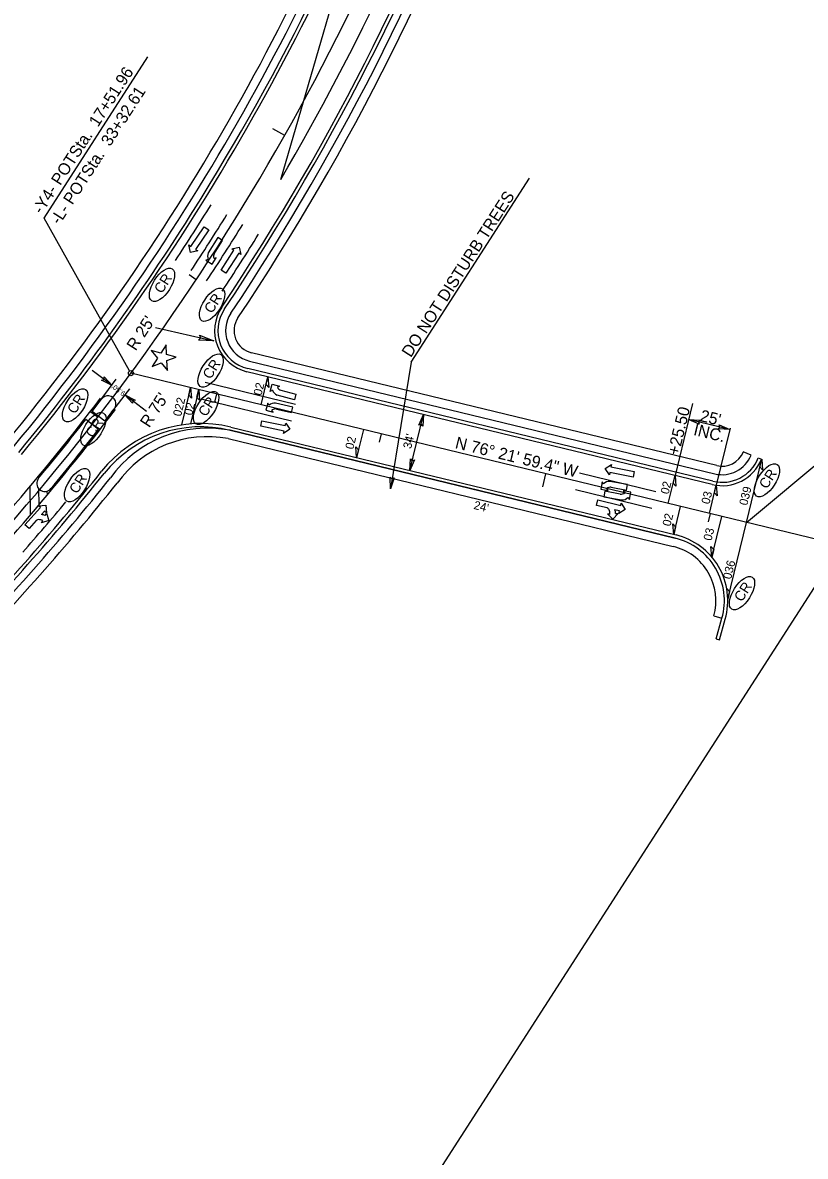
# Model space of a CAD drawing. Extents: x 1974386 to 1979988, y 776712 to 784860.
# Drawn here: x 1977051 to 1977514, y 779824 to 780494 of the extents above; entities that cross this region are included whole.
import ezdxf

# ---------------------------------------------------------------- set-up
doc = ezdxf.new("R2010")
doc.units = 0
for name, color, linetype in [('Prop Conc 2ft 6in Curb and Gutter', 7, 'Continuous'), ('Prop Conc 4in Sidewalk', 7, 'Continuous'), ('Prop Conc 5in Monolithic Keyed In Island', 7, 'Continuous'), ('Prop Conc Drive Drop Type', 7, 'Continuous'), ('Prop Dimension', 7, 'Continuous'), ('Prop Dimension Text', 7, 'Continuous'), ('Prop DSN Text', 7, 'Continuous'), ('Prop EOT', 7, 'Continuous'), ('Prop Horizontal Alignment', 7, 'Continuous'), ('Prop Horizontal Alignment Direction Label', 7, 'Continuous'), ('Prop Horizontal Alignment Station Label', 7, 'Continuous'), ('Prop Horizontal Alignment Tick Large', 7, 'Continuous'), ('Prop Horizontal Alignment Tick Small', 7, 'Continuous'), ('Prop Lane Arrow CELL', 7, 'Continuous'), ('Prop Lane Lines', 7, 'Continuous'), ('Prop RDY Traffic Signal CELL', 7, 'Continuous'), ('Prop Superelevation  Arrow CELL', 7, 'Continuous'), ('Prop Superelevation Label', 7, 'Continuous'), ('Prop Terminator CELL', 7, 'Continuous'), ('Prop WCC CELL', 7, 'Continuous'), ('Scratch_Level_2', 7, 'Continuous'), ('Sheet Layout Plan Border', 7, 'Continuous')]:
    doc.layers.add(name, color=color, linetype=linetype)

msp = doc.modelspace()

# ---------------------------------------------------------------- linework, layer by layer
at = {"layer": 'Prop Conc 2ft 6in Curb and Gutter'}
for p, q in [((1977459.07, 780223.06), (1977184.38, 780289.69)), ((1977173.94, 780253.12), (1977436.77, 780189.37)), ((1977485.82, 780236.94), (1977487.67, 780236.05)), ((1977460.97, 780129.99), (1977464.4, 780142.14)), ((1977460.97, 780129.99), (1977462.9, 780129.45))]:
    msp.add_line(p, q, dxfattribs=at)
for centre, radius, start, end in [((1975987.1, 781115.69), 1376.5, 328.18457, 340.62647), ((1975987.1, 781115.69), 1423.5, 326.24911, 340.62647), ((1975987.1, 781115.69), 1376.5, 320.49711, 328.18457), ((1977189.8, 780312.04), 23, 146.24911, 256.36649), ((1977156.74, 780182.17), 73, 76.36649, 141.40587), ((1977464.49, 780245.41), 23, 256.36649, 338.00929), ((1975987.1, 781115.69), 1423.5, 315.73946, 321.40587), ((1977427.82, 780152.44), 38, 344.27883, 76.36649)]:
    msp.add_arc(centre, radius, start, end, dxfattribs=at)
at = {"layer": 'Prop Conc 4in Sidewalk'}
for p, q in [((1977185.44, 780294.06), (1977460.13, 780227.44)), ((1977461.3, 780232.29), (1977186.62, 780298.92)), ((1977436.77, 780189.37), (1977173.94, 780253.12)), ((1977172.77, 780248.26), (1977435.6, 780184.51)), ((1977172.77, 780248.26), (1977435.6, 780184.51)), ((1977481.64, 780238.49), (1977477, 780240.36)), ((1977459.58, 780143.5), (1977464.4, 780142.14)), ((1977459.58, 780143.5), (1977464.4, 780142.14))]:
    msp.add_line(p, q, dxfattribs=at)
for centre, radius, start, end in [((1975987.1, 781115.69), 1367, 320.45193, 340.62647), ((1975987.1, 781115.69), 1372, 320.5086, 340.62647), ((1975987.1, 781115.69), 1428, 326.24911, 340.62647), ((1975987.1, 781115.69), 1433, 326.24911, 340.62647), ((1977189.8, 780312.04), 18.5, 146.24911, 256.36649), ((1977189.8, 780312.04), 13.5, 146.24911, 256.36649), ((1977160.63, 780183.72), 70.66, 79.13925, 144.17863), ((1977160.63, 780183.72), 70.66, 79.13925, 144.17863), ((1977160.63, 780183.72), 65.66, 79.34999, 144.38937), ((1977160.63, 780183.72), 65.66, 79.34999, 144.38937), ((1977464.49, 780245.41), 13.5, 256.36649, 338.00929), ((1977464.49, 780245.41), 18.5, 256.36649, 338.00929), ((1975987.1, 781115.69), 1428, 315.73946, 321.41478), ((1975987.1, 781115.69), 1428, 315.73946, 321.41478), ((1975987.1, 781115.69), 1433, 315.73946, 321.41478), ((1975987.1, 781115.69), 1433, 315.73946, 321.41478), ((1977427.82, 780152.44), 38, 344.27883, 76.36649), ((1977427.82, 780152.44), 33, 344.27883, 76.36649), ((1977427.82, 780152.44), 33, 344.27883, 76.36649)]:
    msp.add_arc(centre, radius, start, end, dxfattribs=at)
at = {"layer": 'Prop Conc 5in Monolithic Keyed In Island'}
for p, q in [((1977096.29, 780253.7), (1977088.79, 780259.54)), ((1977099.96, 780258.45), (1977092.46, 780264.29))]:
    msp.add_line(p, q, dxfattribs=at)
for centre, radius, start, end in [((1977101.86, 780268.75), 4.75, 322.77439, 142.77439), ((1975987.1, 781115.69), 1395.25, 322.39493, 322.77439), ((1975987.1, 781115.69), 1404.75, 322.39283, 322.77439), ((1975987.1, 781115.69), 1395.25, 320.31886, 322.14854), ((1975987.1, 781115.69), 1404.75, 320.31886, 322.14811), ((1977064.55, 780221.77), 4.75, 140.31886, 320.31886)]:
    msp.add_arc(centre, radius, start, end, dxfattribs=at)
at = {"layer": 'Prop Conc Drive Drop Type'}
msp.add_line((1977337.66, 780213.41), (1977314.34, 780219.06), dxfattribs=at)
at = {"layer": 'Prop Dimension'}
for p, q in [((1977129.82, 780313.77), (1977164.4, 780305.93)), ((1977104.26, 780279.65), (1977092.58, 780288.52)), ((1977092.45, 780264.29), (1977106.72, 780283.38)), ((1977099.96, 780258.45), (1977114.76, 780277.64)), ((1977124.61, 780264.31), (1977111.74, 780274.09)), ((1977446.99, 780269.01), (1977436.66, 780226.44)), ((1977280.11, 780229.42), (1977288.12, 780262.47)), ((1977468.98, 780253.63), (1977444.68, 780259.52)), ((1977469.16, 780254.38), (1977460.98, 780220.66))]:
    msp.add_line(p, q, dxfattribs=at)
at = {"layer": 'Prop DSN Text'}
for q in [(1977350.71, 780402.12), (1977268.62, 780218.57)]:
    msp.add_line((1977280.93, 780293.47), q, dxfattribs=at)
at = {"layer": 'Prop EOT'}
for p, q in [((1977458.59, 780221.12), (1977183.91, 780287.74)), ((1977174.42, 780255.06), (1977437.25, 780191.31)), ((1977462.9, 780129.45), (1977466.32, 780141.6))]:
    msp.add_line(p, q, dxfattribs=at)
for centre, radius, start, end in [((1975987.1, 781115.69), 1378.5, 320.50095, 340.62647), ((1975987.1, 781115.69), 1421.5, 326.24911, 340.61773), ((1977189.8, 780312.04), 25, 146.24911, 256.36649), ((1977156.74, 780182.17), 75, 76.36649, 141.40587), ((1977464.49, 780245.41), 25, 256.36649, 338.00929), ((1975987.1, 781115.69), 1421.5, 315.73946, 321.40587), ((1977427.82, 780152.44), 40, 344.27883, 76.36649)]:
    msp.add_arc(centre, radius, start, end, dxfattribs=at)
at = {"layer": 'Prop Horizontal Alignment'}
msp.add_line((1977701.03, 780144.83), (1977115.39, 780286.87), dxfattribs=at)
msp.add_arc((1975987.1, 781115.69), 1400, 315.73946, 340.62647, dxfattribs=at)
at = {"layer": 'Prop Horizontal Alignment Station Label'}
for p, q in [((1977064.11, 780378.45), (1977125.46, 780473.84)), ((1977114.66, 780288.18), (1977064.11, 780378.45)), ((1977478.82, 780198.72), (1977566.67, 780272.16))]:
    msp.add_line(p, q, dxfattribs=at)
msp.add_circle((1977115.39, 780286.87), 1.5, dxfattribs=at)
at = {"layer": 'Prop Horizontal Alignment Tick Large'}
for p, q in [((1977206.2, 780427.36), (1977199.23, 780431.3)), ((1977360.25, 780227.48), (1977358.37, 780219.7))]:
    msp.add_line(p, q, dxfattribs=at)
at = {"layer": 'Prop Horizontal Alignment Tick Small'}
for p, q in [((1977153.97, 780342.11), (1977149.8, 780344.88)), ((1977165.89, 780274.62), (1977164.71, 780269.76)), ((1977095.78, 780260.81), (1977091.82, 780263.86)), ((1977263.07, 780251.05), (1977261.89, 780246.19)), ((1977457.43, 780203.91), (1977456.26, 780199.05)), ((1977457.43, 780203.91), (1977456.26, 780199.05)), ((1977457.43, 780203.91), (1977456.26, 780199.05))]:
    msp.add_line(p, q, dxfattribs=at)
at = {"layer": 'Prop Lane Arrow CELL'}
for p, q in [((1977150.84, 780361.78), (1977158.65, 780373.4)), ((1977158.65, 780373.4), (1977161.39, 780371.56)), ((1977161.39, 780371.56), (1977153.58, 780359.94)), ((1977166.66, 780366.96), (1977161.09, 780358.01)), ((1977169.46, 780365.22), (1977166.66, 780366.96)), ((1977150.49, 780358.22), (1977149.59, 780362.62)), ((1977149.59, 780362.62), (1977150.84, 780361.78)), ((1977153.58, 780359.94), (1977154.82, 780359.1)), ((1977164.63, 780357.45), (1977169.46, 780365.22)), ((1977168.65, 780347.79), (1977176.26, 780359.55)), ((1977175, 780360.36), (1977179.31, 780361.32)), ((1977176.26, 780359.55), (1977175, 780360.36)), ((1977179.31, 780361.32), (1977180.29, 780356.94)), ((1977154.82, 780359.1), (1977150.49, 780358.22)), ((1977161.05, 780353.97), (1977159.6, 780353.63)), ((1977159.6, 780353.63), (1977163.31, 780351.26)), ((1977163.31, 780351.26), (1977165.73, 780355.06)), ((1977165.73, 780355.06), (1977164.28, 780354.72)), ((1977179.03, 780357.75), (1977171.42, 780346)), ((1977180.29, 780356.94), (1977179.03, 780357.75)), ((1977171.42, 780346), (1977168.65, 780347.79)), ((1977197.7, 780276.15), (1977198.8, 780280.41)), ((1977198.8, 780280.41), (1977203.16, 780279.29)), ((1977203.16, 780279.29), (1977201.87, 780278.55)), ((1977198.99, 780276.89), (1977197.7, 780276.15)), ((1977211.95, 780271.21), (1977201.77, 780273.96)), ((1977203.98, 780276.78), (1977212.82, 780274.39)), ((1977212.82, 780274.39), (1977211.95, 780271.21)), ((1977196.15, 780269.21), (1977195.09, 780264.94)), ((1977196.93, 780267.95), (1977196.15, 780269.21)), ((1977211.04, 780266.78), (1977200.77, 780269.2)), ((1977201.38, 780265.67), (1977210.28, 780263.57)), ((1977210.28, 780263.57), (1977211.04, 780266.78)), ((1977195.09, 780264.94), (1977199.46, 780263.86)), ((1977199.46, 780263.86), (1977198.68, 780265.12)), ((1977192.11, 780255.49), (1977192.78, 780258.73)), ((1977205.83, 780252.68), (1977192.11, 780255.49)), ((1977192.78, 780258.73), (1977206.49, 780255.91)), ((1977209.26, 780253.71), (1977205.53, 780251.21)), ((1977205.53, 780251.21), (1977205.83, 780252.68)), ((1977206.49, 780255.91), (1977206.79, 780257.38)), ((1977206.79, 780257.38), (1977209.26, 780253.71)), ((1977395.43, 780230.48), (1977399.16, 780232.98)), ((1977399.16, 780232.98), (1977398.86, 780231.51)), ((1977397.89, 780226.81), (1977395.43, 780230.48)), ((1977398.19, 780228.28), (1977397.89, 780226.81)), ((1977411.91, 780225.46), (1977398.19, 780228.28)), ((1977398.86, 780231.51), (1977412.57, 780228.7)), ((1977412.57, 780228.7), (1977411.91, 780225.46)), ((1977393.6, 780222.72), (1977392.78, 780218.39)), ((1977394.45, 780221.5), (1977393.6, 780222.72)), ((1977397.2, 780217.55), (1977396.35, 780218.77)), ((1977408.6, 780221.09), (1977398.22, 780222.95)), ((1977399.01, 780219.46), (1977408.02, 780217.84)), ((1977408.02, 780217.84), (1977408.6, 780221.09)), ((1977390.39, 780208.8), (1977391.17, 780212.01)), ((1977391.17, 780212.01), (1977404.58, 780208.72)), ((1977392.78, 780218.39), (1977397.2, 780217.55)), ((1977395.31, 780217.09), (1977394.73, 780213.84)), ((1977394.73, 780213.84), (1977405.11, 780211.98)), ((1977404.32, 780215.48), (1977395.31, 780217.09)), ((1977410.55, 780216.54), (1977406.13, 780217.38)), ((1977406.13, 780217.38), (1977406.98, 780216.17)), ((1977408.88, 780213.44), (1977409.72, 780212.22)), ((1977409.72, 780212.22), (1977410.55, 780216.54)), ((1977052.79, 780197.28), (1977061.92, 780207.62)), ((1977060.8, 780208.61), (1977065.21, 780208.85)), ((1977061.92, 780207.62), (1977060.8, 780208.61)), ((1977064.39, 780205.44), (1977062.51, 780203.3)), ((1977065.52, 780204.44), (1977064.39, 780205.44)), ((1977065.21, 780208.85), (1977065.52, 780204.44)), ((1977396.65, 780207.26), (1977390.39, 780208.8)), ((1977403.79, 780205.51), (1977401.02, 780206.19)), ((1977407.19, 780206.37), (1977403.43, 780204.05)), ((1977403.43, 780204.05), (1977403.79, 780205.51)), ((1977404.58, 780208.72), (1977404.93, 780210.17)), ((1977404.93, 780210.17), (1977407.19, 780206.37)), ((1977059.53, 780199.93), (1977055.26, 780195.09)), ((1977066.9, 780199.89), (1977062.7, 780198.46)), ((1977062.7, 780198.46), (1977063.33, 780199.77)), ((1977064.81, 780202.73), (1977065.47, 780204.09)), ((1977065.47, 780204.09), (1977066.9, 780199.89)), ((1977396.82, 780203.77), (1977398.28, 780203.83)), ((1977400.04, 780200.72), (1977396.82, 780203.77)), ((1977403.09, 780203.93), (1977400.04, 780200.72)), ((1977401.59, 780203.89), (1977403.09, 780203.93)), ((1977055.26, 780195.09), (1977052.79, 780197.28))]:
    msp.add_line(p, q, dxfattribs=at)
for centre, radius, start, end in [((1977165.9, 780355.94), 5.25, 156.78047, 202.09216), ((1977167.39, 780355.72), 3.27, 148.1044, 197.76257), ((1977203.89, 780278.75), 5.25, 200.86938, 246.18108), ((1977204.82, 780279.93), 3.27, 205.19898, 254.85715), ((1977200.36, 780263.98), 5.25, 85.40152, 130.71321), ((1977200.62, 780262.5), 3.27, 76.72544, 126.38362), ((1977398.08, 780217.72), 5.25, 88.49449, 133.80619), ((1977398.43, 780216.25), 3.27, 79.81842, 129.47659), ((1977404.9, 780218.68), 3.27, 259.81842, 309.47659), ((1977405.25, 780217.21), 5.25, 268.49449, 313.80619), ((1977395.45, 780205.04), 2.52, 25.27738, 61.58938), ((1977393.84, 780203.99), 4.43, 357.91391, 28.76747), ((1977397.15, 780204.06), 4.43, 357.7951, 28.6737), ((1977060.94, 780197.83), 2.52, 87.62766, 123.93966), ((1977061.13, 780195.92), 4.43, 60.26419, 91.11775), ((1977062.6, 780198.88), 4.43, 60.14538, 91.02398)]:
    msp.add_arc(centre, radius, start, end, dxfattribs=at)
at = {"layer": 'Prop Lane Lines'}
for p, q in [((1977212.6, 780268.44), (1977159.29, 780281.37)), ((1977156.93, 780271.65), (1977210.24, 780258.72)), ((1977425.35, 780216.83), (1977380.2, 780227.78)), ((1977056.2, 780203.3), (1977055.98, 780220.08)), ((1977061.13, 780209.11), (1977061, 780218.61)), ((1977066.05, 780214.97), (1977066.02, 780217.25)), ((1977377.85, 780218.07), (1977422.99, 780207.12))]:
    msp.add_line(p, q, dxfattribs=at)
for radius, start, end in [(1383.5, 326.57123, 328.18415), (1394.5, 326.57123, 328.18415), (1405.5, 326.57123, 328.18415), (1416.5, 326.57123, 328.18415), (1394.5, 315.73946, 322.77439), (1405.5, 315.73946, 322.77439), (1416.5, 318.71501, 320.29496)]:
    msp.add_arc((1975987.1, 781115.69), radius, start, end, dxfattribs=at)
at = {"layer": 'Prop RDY Traffic Signal CELL'}
msp.add_lwpolyline([(1977131.03, 780295.74), (1977127.89, 780290.86), (1977133.3, 780292.96), (1977136.98, 780288.46), (1977136.65, 780294.27), (1977142.07, 780296.38), (1977136.45, 780297.85), (1977136.12, 780303.65), (1977132.98, 780298.77), (1977127.35, 780300.24), (1977131.03, 780295.74)], dxfattribs=at)
at = {"layer": 'Prop Superelevation  Arrow CELL'}
for p, q in [((1977192.32, 780268.21), (1977196.32, 780284.73)), ((1977150.6, 780278.33), (1977145.26, 780256.29)), ((1977155.46, 780277.15), (1977150.55, 780256.92)), ((1977252.64, 780253.58), (1977248.64, 780237.06)), ((1977478.82, 780198.72), (1977487.86, 780236.02)), ((1977432.65, 780209.92), (1977436.66, 780226.44)), ((1977456.95, 780204.02), (1977460.98, 780220.66)), ((1977435.94, 780191.63), (1977439.94, 780208.15)), ((1977458.41, 780178.21), (1977464.24, 780202.26)), ((1977467.81, 780153.33), (1977478.82, 780198.72))]:
    msp.add_line(p, q, dxfattribs=at)
for points in [[(1977196.32, 780284.73), (1977196.85, 780278.43), (1977195.23, 780280.24)], [(1977150.6, 780278.33), (1977151.13, 780272.03), (1977149.51, 780273.83)], [(1977155.46, 780277.15), (1977155.99, 780270.85), (1977154.37, 780272.65)], [(1977248.64, 780237.06), (1977248.11, 780243.36), (1977249.73, 780241.55)], [(1977487.86, 780236.02), (1977488.39, 780229.72), (1977486.77, 780231.53)], [(1977436.66, 780226.44), (1977437.19, 780220.14), (1977435.57, 780221.94)], [(1977460.98, 780220.66), (1977461.51, 780214.36), (1977459.89, 780216.17)], [(1977435.94, 780191.63), (1977435.41, 780197.93), (1977437.03, 780196.12)], [(1977458.41, 780178.21), (1977457.88, 780184.51), (1977459.5, 780182.71)], [(1977467.81, 780153.33), (1977467.28, 780159.64), (1977468.9, 780157.83)]]:
    msp.add_lwpolyline(points, close=True, dxfattribs=at)
at = {"layer": 'Prop Terminator CELL'}
for points in [[(1977155.97, 780309.43), (1977164.4, 780305.93), (1977155.22, 780306.37), (1977156.7, 780307.68)], [(1977099.58, 780284.66), (1977104.26, 780279.65), (1977098.12, 780282.8), (1977099.54, 780283.24)], [(1977116.41, 780269.08), (1977111.74, 780274.09), (1977117.87, 780270.94), (1977116.46, 780270.51)], [(1977285.4, 780256.18), (1977288.12, 780262.47), (1977287.69, 780255.59), (1977286.73, 780256.71)], [(1977450.97, 780256.8), (1977444.68, 780259.52), (1977451.56, 780259.09), (1977450.44, 780258.13)], [(1977462.69, 780256.35), (1977468.98, 780253.63), (1977462.1, 780254.06), (1977463.22, 780255.03)], [(1977282.83, 780235.71), (1977280.11, 780229.42), (1977280.54, 780236.3), (1977281.5, 780235.18)], [(1977270.86, 780225.05), (1977268.62, 780218.57), (1977268.53, 780225.47), (1977269.58, 780224.42)]]:
    msp.add_lwpolyline(points, close=True, dxfattribs=at)
at = {"layer": 'Prop WCC CELL'}
for centre in [(1977133.76, 780339.05), (1977163.33, 780327.29), (1977162.43, 780288.42), (1977082.45, 780267.88), (1977159.79, 780266.3), (1977093.22, 780253.79), (1977490.92, 780223.59), (1977083.63, 780220.74), (1977476.21, 780156.91)]:
    msp.add_ellipse(centre, major_axis=(6.07, 9.43), ratio=0.462467, dxfattribs=at)
at = {"layer": 'Scratch_Level_2'}
msp.add_line((1977203.85, 780401.24), (1977333.59, 780846.18), dxfattribs=at)
msp.add_arc((1975987.1, 781115.69), 1411, 329.5795, 340.62647, dxfattribs=at)
at = {"layer": 'Sheet Layout Plan Border'}
msp.add_lwpolyline([(1977111.11, 779526.05), (1977868.38, 780703.57), (1976985.24, 781271.52), (1976227.97, 780094)], close=True, dxfattribs=at)

# ---------------------------------------------------------------- texts
at = {"layer": 'Prop Dimension'}
msp.add_text("9.50'", height=2.953, rotation=142.77978, dxfattribs=at).set_placement((1977112.45, 780275.39))
at = {"layer": 'Prop Dimension Text'}
for s, height, rotation, p in [("R 25'", 7, 57.25495, (1977118.23, 780299.65)), ("R 75'", 7, 57.25495, (1977126.18, 780254.26)), ('+25.50', 7, 76.36649, (1977438.84, 780237.94)), ("25'", 7, 346.36649, (1977450.95, 780258.65)), ('INC.', 7, 346.36649, (1977447.14, 780250.44)), ("34'", 5, 76.36649, (1977280.81, 780241.85)), ("24'", 5, 346.36649, (1977317.46, 780206.74))]:
    msp.add_text(s, height=height, rotation=rotation, dxfattribs=at).set_placement(p)
at = {"layer": 'Prop DSN Text'}
msp.add_text('DO NOT DISTURB TREES', height=7, rotation=57.25497, dxfattribs=at).set_placement((1977280.66, 780295.74))
at = {"layer": 'Prop Horizontal Alignment Direction Label'}
msp.add_text('N 76%%d 21\' 59.4" W', height=7, rotation=346.36649, dxfattribs=at).set_placement((1977306.43, 780242.67))
at = {"layer": 'Prop Horizontal Alignment Station Label'}
for s, p in [('-Y4- POTSta.  17+51.96', (1977062.68, 780380.31)), ('-L- POTSta.  33+32.61', (1977073.21, 780374.1))]:
    msp.add_text(s, height=7, rotation=57.16832, dxfattribs=at).set_placement(p)
at = {"layer": 'Prop Superelevation Label'}
for s, p in [('02', (1977192.51, 780273.36)), ('022', (1977144.98, 780261.02)), ('02', (1977151.53, 780261.61)), ('02', (1977246.67, 780241.56)), ('02', (1977432.85, 780215.07)), ('039', (1977479.3, 780208.42)), ('03', (1977456.93, 780209.17)), ('02', (1977433.97, 780196.13)), ('03', (1977458.17, 780187.56)), ('036', (1977469.74, 780164.83))]:
    msp.add_text(s, height=5, rotation=76.36649, dxfattribs=at).set_placement(p)
at = {"layer": 'Prop WCC CELL'}
for rotation, p in [(57.25497, (1977133.7, 780333.49)), (57.25497, (1977163.26, 780321.73)), (57.25497, (1977162.36, 780282.86)), (57.25497, (1977082.38, 780262.32)), (57.25497, (1977159.73, 780260.74)), (57.25497, (1977093.16, 780248.23)), (57.25497, (1977083.56, 780215.18)), (57.25495, (1977490.85, 780218.03)), (57.25495, (1977476.14, 780151.35))]:
    msp.add_text('CR', height=6, rotation=rotation, dxfattribs=at).set_placement(p)

doc.saveas('drawing.dxf')
